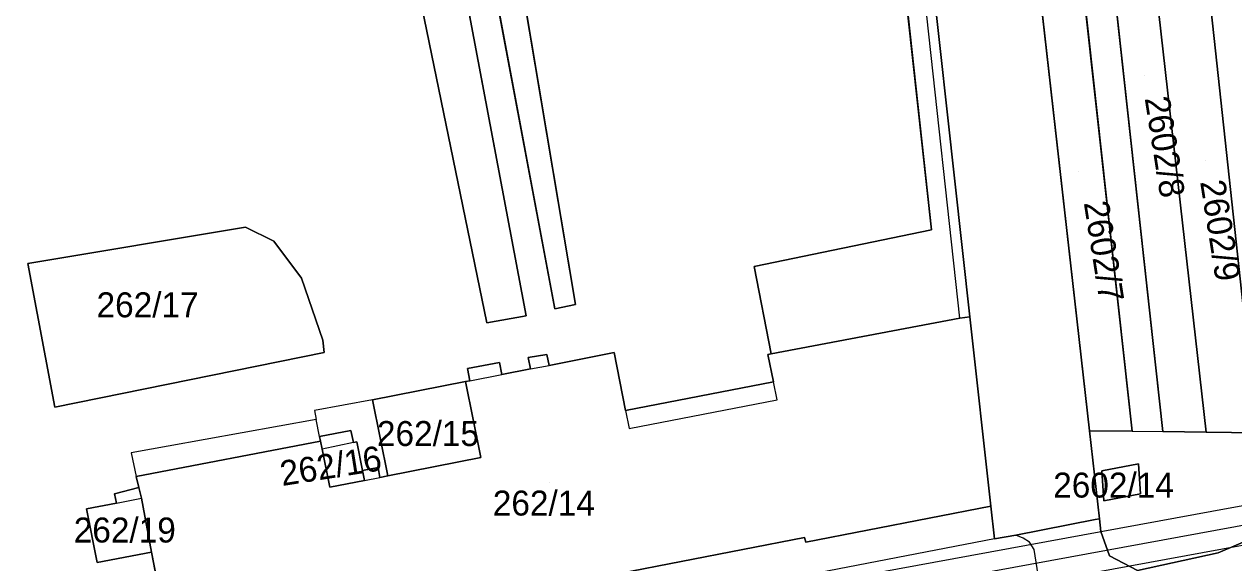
# Model space of a CAD drawing. Extents: x -263423 to -261326, y -1240067 to -1237864.
# Drawn here: x -263340.5 to -263243.6, y -1239342.6 to -1239299.5 of the extents above; entities that cross this region are included whole.
import ezdxf

# ---------------------------------------------------------------- set-up
doc = ezdxf.new("R2010")
doc.units = 0
for name, color, linetype in [('body_kn', 7, 'Continuous'), ('kladpar_druhypozemkov', 7, 'Continuous'), ('kladpar_hranice', 7, 'Continuous'), ('kladpar_parcelnecisla', 7, 'Continuous'), ('kladpar_plochy', 7, 'Continuous'), ('linie', 7, 'Continuous'), ('tarchy_linie', 7, 'Continuous'), ('zappar_hrandruhpozemk', 7, 'Continuous')]:
    doc.layers.add(name, color=color, linetype=linetype)

msp = doc.modelspace()

# ---------------------------------------------------------------- linework, layer by layer
at = {"layer": 'body_kn'}
for p, q in [((-263322.75, -1239315.73), (-263322.75, -1239315.73)), ((-263267.78, -1239315.94), (-263267.78, -1239315.94)), ((-263320.48, -1239316.83), (-263320.48, -1239316.83)), ((-263340.2, -1239318.63), (-263340.2, -1239318.63)), ((-263340.2, -1239318.63), (-263340.2, -1239318.63)), ((-263281.99, -1239318.86), (-263281.99, -1239318.86)), ((-263318.28, -1239319.81), (-263318.28, -1239319.81)), ((-263297.96, -1239322.25), (-263297.96, -1239322.25)), ((-263296.33, -1239321.92), (-263296.33, -1239321.92)), ((-263303.42, -1239323.37), (-263303.42, -1239323.37)), ((-263300.28, -1239322.81), (-263300.28, -1239322.81)), ((-263300.28, -1239322.81), (-263300.28, -1239322.81)), ((-263265.51, -1239323.01), (-263265.51, -1239323.01)), ((-263265.51, -1239323.01), (-263265.51, -1239323.01)), ((-263264.71, -1239322.89), (-263264.71, -1239322.89)), ((-263316.57, -1239324.78), (-263316.57, -1239324.78)), ((-263316.46, -1239325.77), (-263316.46, -1239325.77)), ((-263302.41, -1239326.55), (-263302.41, -1239326.55)), ((-263300.1, -1239326.17), (-263300.1, -1239326.17)), ((-263298.61, -1239325.92), (-263298.61, -1239325.92)), ((-263293.21, -1239325.77), (-263293.21, -1239325.77)), ((-263280.9, -1239325.92), (-263280.9, -1239325.92)), ((-263280.65, -1239325.87), (-263280.65, -1239325.87)), ((-263304.97, -1239327.05), (-263304.97, -1239327.05)), ((-263302.22, -1239327.53), (-263302.22, -1239327.53)), ((-263299.93, -1239327.08), (-263299.93, -1239327.08)), ((-263299.93, -1239327.08), (-263299.93, -1239327.08)), ((-263298.44, -1239326.79), (-263298.44, -1239326.79)), ((-263305.12, -1239328.09), (-263305.12, -1239328.09)), ((-263304.78, -1239328.03), (-263304.78, -1239328.03)), ((-263304.78, -1239328.03), (-263304.78, -1239328.03)), ((-263280.45, -1239328.1), (-263280.45, -1239328.1)), ((-263338.04, -1239330.14), (-263338.04, -1239330.14)), ((-263317.23, -1239330.4), (-263317.23, -1239330.4)), ((-263317.23, -1239330.4), (-263317.23, -1239330.4)), ((-263312.58, -1239329.55), (-263312.58, -1239329.55)), ((-263312.58, -1239329.55), (-263312.58, -1239329.55)), ((-263292.31, -1239330.41), (-263292.31, -1239330.41)), ((-263292.31, -1239330.41), (-263292.31, -1239330.41)), ((-263280.15, -1239329.55), (-263280.15, -1239329.55)), ((-263280.15, -1239329.55), (-263280.15, -1239329.55)), ((-263317.09, -1239331.13), (-263317.09, -1239331.13)), ((-263317.09, -1239331.13), (-263317.09, -1239331.13)), ((-263314.31, -1239332.01), (-263314.31, -1239332.01)), ((-263292.02, -1239331.86), (-263292.02, -1239331.86)), ((-263292.02, -1239331.86), (-263292.02, -1239331.86)), ((-263255.13, -1239332.03), (-263255.13, -1239332.03)), ((-263251.72, -1239332.06), (-263251.72, -1239332.06)), ((-263251.72, -1239332.06), (-263251.72, -1239332.06)), ((-263249.26, -1239332.09), (-263249.26, -1239332.09)), ((-263245.77, -1239332.15), (-263245.77, -1239332.15)), ((-263316.82, -1239332.5), (-263316.82, -1239332.5)), ((-263316.82, -1239332.5), (-263316.82, -1239332.5)), ((-263316.75, -1239332.86), (-263316.75, -1239332.86)), ((-263316.75, -1239332.86), (-263316.75, -1239332.86)), ((-263314.11, -1239332.97), (-263314.11, -1239332.97)), ((-263314.11, -1239332.97), (-263314.11, -1239332.97)), ((-263313.83, -1239332.91), (-263313.83, -1239332.91)), ((-263331.93, -1239333.8), (-263331.93, -1239333.8)), ((-263331.93, -1239333.8), (-263331.93, -1239333.8)), ((-263316.62, -1239333.49), (-263316.62, -1239333.49)), ((-263303.89, -1239334.18), (-263303.89, -1239334.18)), ((-263313.38, -1239335.22), (-263313.38, -1239335.22)), ((-263312.14, -1239334.98), (-263312.14, -1239334.98)), ((-263254.14, -1239335.23), (-263254.14, -1239335.23)), ((-263254.14, -1239335.23), (-263254.14, -1239335.23)), ((-263251.2, -1239334.68), (-263251.2, -1239334.68)), ((-263331.53, -1239335.68), (-263331.53, -1239335.68)), ((-263313.22, -1239336), (-263313.22, -1239336)), ((-263313.22, -1239336), (-263313.22, -1239336)), ((-263311.99, -1239335.76), (-263311.99, -1239335.76)), ((-263311.35, -1239335.63), (-263311.35, -1239335.63)), ((-263311.35, -1239335.63), (-263311.35, -1239335.63)), ((-263333.26, -1239337.07), (-263333.26, -1239337.07)), ((-263331.3, -1239336.58), (-263331.3, -1239336.58)), ((-263316, -1239336.54), (-263316, -1239336.54)), ((-263251.03, -1239337.08), (-263251.03, -1239337.08)), ((-263333.11, -1239337.82), (-263333.11, -1239337.82)), ((-263333.11, -1239337.82), (-263333.11, -1239337.82)), ((-263331.09, -1239337.42), (-263331.09, -1239337.42)), ((-263331.09, -1239337.42), (-263331.09, -1239337.42)), ((-263263.04, -1239338.07), (-263263.04, -1239338.07)), ((-263253.97, -1239337.63), (-263253.97, -1239337.63)), ((-263243.72, -1239338.18), (-263243.72, -1239338.18)), ((-263335.5, -1239338.29), (-263335.5, -1239338.29)), ((-263254.67, -1239339.14), (-263254.67, -1239339.14)), ((-263254.67, -1239339.14), (-263254.67, -1239339.14)), ((-263254.34, -1239339.08), (-263254.34, -1239339.08)), ((-263254.23, -1239340.09), (-263254.23, -1239340.09)), ((-263277.97, -1239340.58), (-263277.97, -1239340.58)), ((-263277.85, -1239340.95), (-263277.85, -1239340.95)), ((-263262.75, -1239340.68), (-263262.75, -1239340.68)), ((-263262.75, -1239340.68), (-263262.75, -1239340.68)), ((-263261.02, -1239340.38), (-263261.02, -1239340.38)), ((-263260.45, -1239340.64), (-263260.45, -1239340.64)), ((-263259.94, -1239340.96), (-263259.94, -1239340.96)), ((-263330.29, -1239341.75), (-263330.29, -1239341.75)), ((-263259.57, -1239341.53), (-263259.57, -1239341.53)), ((-263253.53, -1239342.05), (-263253.53, -1239342.05)), ((-263244.83, -1239341.82), (-263244.83, -1239341.82)), ((-263334.65, -1239342.57), (-263334.65, -1239342.57))]:
    msp.add_line(p, q, dxfattribs=at)
at = {"layer": 'kladpar_druhypozemkov'}
for p, q in [((-263250.71, -1239303.58), (-263250.71, -1239303.58)), ((-263245.82, -1239310.4), (-263245.82, -1239310.4)), ((-263256.04, -1239311.29), (-263256.04, -1239311.29)), ((-263329.96, -1239320.82), (-263329.96, -1239320.82)), ((-263307.62, -1239331.44), (-263307.62, -1239331.44)), ((-263314.67, -1239334.11), (-263314.67, -1239334.11)), ((-263298.44, -1239336.19), (-263298.44, -1239336.19)), ((-263252.48, -1239335.84), (-263252.48, -1239335.84)), ((-263332.65, -1239339.19), (-263332.65, -1239339.19))]:
    msp.add_line(p, q, dxfattribs=at)
at = {"layer": 'kladpar_hranice'}
for points in [[(-263254.67, -1239339.14), (-263261.02, -1239340.38), (-263262.75, -1239340.68), (-263263.04, -1239338.07), (-263264.71, -1239322.89), (-263268.9, -1239284.96), (-263273.11, -1239246.76), (-263274.93, -1239230.45), (-263274.97, -1239230.07), (-263276.29, -1239218.08), (-263279.7, -1239187.24), (-263281.03, -1239175.14), (-263282.73, -1239159.77), (-263283.91, -1239149.05), (-263286.63, -1239124.36), (-263290.39, -1239090.28)], [(-263228.94, -1239359.01), (-263232.6, -1239324.94), (-263236.39, -1239289.06), (-263237.7, -1239277.07), (-263241.63, -1239244.14), (-263243.01, -1239243.11), (-263245.1, -1239242.75), (-263246.01, -1239242.84), (-263251.52, -1239243.4), (-263255.64, -1239243.86), (-263258.95, -1239244.24), (-263261.36, -1239244.51), (-263263.54, -1239244.9), (-263264.39, -1239245.64), (-263264.94, -1239247.51), (-263262.98, -1239262.22), (-263262.49, -1239266.88), (-263255.13, -1239332.03), (-263254.34, -1239339.08), (-263254.67, -1239339.14)], [(-263244.09, -1239277.88), (-263247.38, -1239247.93), (-263247.85, -1239246.23), (-263249.91, -1239245.35), (-263251.31, -1239245.48), (-263251.52, -1239243.4), (-263246.01, -1239242.84), (-263242.19, -1239277.63), (-263237.7, -1239277.07), (-263236.39, -1239289.06), (-263240.85, -1239289.58), (-263236.07, -1239332.28), (-263234.28, -1239332.3), (-263236.08, -1239335.51), (-263237.48, -1239337.31), (-263240.67, -1239340.05), (-263244.83, -1239341.82), (-263251.27, -1239343.22), (-263253.53, -1239342.05), (-263254.23, -1239340.09), (-263254.34, -1239339.08), (-263255.13, -1239332.03)], [(-263255.13, -1239332.03), (-263251.72, -1239332.06), (-263258.71, -1239268.54), (-263262.49, -1239266.88), (-263262.98, -1239262.22), (-263259.18, -1239263.91), (-263261.36, -1239244.51)], [(-263261.36, -1239244.51), (-263258.95, -1239244.24), (-263256.64, -1239265.03), (-263253.21, -1239266.52), (-263248.84, -1239268.41), (-263246.58, -1239269.39), (-263248.21, -1239273.13), (-263252.68, -1239271.18), (-263256.12, -1239269.67), (-263249.26, -1239332.09), (-263245.77, -1239332.15), (-263241.72, -1239332.2), (-263238.03, -1239332.26), (-263242.78, -1239289.8), (-263246.26, -1239290.22), (-263247.62, -1239278.34), (-263244.09, -1239277.88)], [(-263262.49, -1239266.88), (-263258.71, -1239268.54), (-263251.72, -1239332.06), (-263255.13, -1239332.03), (-263262.49, -1239266.88)], [(-263307.79, -1239270), (-263297.96, -1239322.25), (-263296.33, -1239321.92), (-263301.05, -1239293.74)], [(-263301.05, -1239293.74), (-263296.33, -1239321.92), (-263297.96, -1239322.25), (-263307.79, -1239270)], [(-263256.12, -1239269.67), (-263252.68, -1239271.18), (-263245.77, -1239332.15), (-263249.26, -1239332.09), (-263256.12, -1239269.67)], [(-263252.68, -1239271.18), (-263248.21, -1239273.13), (-263247.62, -1239278.34), (-263246.26, -1239290.22), (-263241.72, -1239332.2), (-263245.77, -1239332.15), (-263252.68, -1239271.18)], [(-263303.42, -1239323.37), (-263300.28, -1239322.81), (-263309.63, -1239273.2), (-263313.62, -1239273.77), (-263303.42, -1239323.37)], [(-263300.28, -1239322.81), (-263303.42, -1239323.37), (-263313.62, -1239273.77), (-263309.63, -1239273.2), (-263300.28, -1239322.81)], [(-263268.9, -1239284.96), (-263264.71, -1239322.89), (-263265.51, -1239323.01), (-263280.65, -1239325.87), (-263281.99, -1239318.86), (-263267.78, -1239315.94), (-263270.77, -1239288.79)], [(-263270.77, -1239288.79), (-263267.78, -1239315.94), (-263281.99, -1239318.86), (-263280.65, -1239325.87), (-263280.9, -1239325.92), (-263280.45, -1239328.1), (-263292.31, -1239330.41), (-263293.21, -1239325.77), (-263298.44, -1239326.79), (-263298.61, -1239325.92), (-263300.1, -1239326.17), (-263299.93, -1239327.08), (-263302.22, -1239327.53), (-263302.41, -1239326.55), (-263304.97, -1239327.05), (-263304.78, -1239328.03), (-263305.12, -1239328.09), (-263312.58, -1239329.55), (-263311.35, -1239335.63), (-263311.99, -1239335.76), (-263312.14, -1239334.98), (-263313.38, -1239335.22), (-263313.83, -1239332.91), (-263314.11, -1239332.97), (-263314.31, -1239332.01), (-263316.82, -1239332.5), (-263316.75, -1239332.86), (-263331.53, -1239335.68), (-263331.3, -1239336.58), (-263333.26, -1239337.07), (-263333.11, -1239337.82), (-263335.5, -1239338.29), (-263334.65, -1239342.57), (-263330.29, -1239341.75), (-263328.77, -1239349.65)], [(-263246.26, -1239290.22), (-263242.78, -1239289.8), (-263238.03, -1239332.26), (-263241.72, -1239332.2), (-263246.26, -1239290.22)], [(-263322.75, -1239315.73), (-263340.2, -1239318.63), (-263338.04, -1239330.14), (-263316.46, -1239325.77), (-263316.57, -1239324.78), (-263318.28, -1239319.81), (-263320.48, -1239316.83), (-263322.75, -1239315.73)], [(-263340.2, -1239318.63), (-263322.75, -1239315.73), (-263320.48, -1239316.83), (-263318.28, -1239319.81), (-263316.57, -1239324.78), (-263316.46, -1239325.77), (-263338.04, -1239330.14), (-263340.2, -1239318.63)], [(-263328.77, -1239349.65), (-263330.29, -1239341.75), (-263331.09, -1239337.42), (-263331.3, -1239336.58), (-263331.53, -1239335.68), (-263316.75, -1239332.86), (-263316.62, -1239333.49), (-263316, -1239336.54), (-263313.22, -1239336), (-263313.38, -1239335.22), (-263312.14, -1239334.98), (-263311.99, -1239335.76), (-263311.35, -1239335.63), (-263303.89, -1239334.18), (-263305.12, -1239328.09), (-263304.78, -1239328.03), (-263304.97, -1239327.05), (-263302.41, -1239326.55), (-263302.22, -1239327.53), (-263299.93, -1239327.08), (-263300.1, -1239326.17), (-263298.61, -1239325.92), (-263298.44, -1239326.79), (-263293.21, -1239325.77), (-263292.31, -1239330.41), (-263280.45, -1239328.1), (-263280.9, -1239325.92), (-263280.65, -1239325.87), (-263265.51, -1239323.01), (-263264.71, -1239322.89), (-263263.04, -1239338.07), (-263277.85, -1239340.95), (-263277.97, -1239340.58), (-263292.78, -1239343.45)], [(-263292.78, -1239343.45), (-263277.97, -1239340.58), (-263277.85, -1239340.95), (-263263.04, -1239338.07), (-263262.75, -1239340.68), (-263261.02, -1239340.38), (-263254.67, -1239339.14), (-263254.34, -1239339.08), (-263254.23, -1239340.09), (-263253.53, -1239342.05), (-263251.27, -1239343.22), (-263244.83, -1239341.82), (-263240.67, -1239340.05), (-263237.48, -1239337.31), (-263236.08, -1239335.51), (-263234.28, -1239332.3), (-263233.24, -1239329.66), (-263232.6, -1239324.94), (-263228.94, -1239359.01)], [(-263311.35, -1239335.63), (-263312.58, -1239329.55), (-263305.12, -1239328.09), (-263303.89, -1239334.18), (-263311.35, -1239335.63)], [(-263316.75, -1239332.86), (-263316.82, -1239332.5), (-263314.31, -1239332.01), (-263314.11, -1239332.97), (-263313.83, -1239332.91), (-263313.38, -1239335.22), (-263313.22, -1239336), (-263316, -1239336.54), (-263316.62, -1239333.49), (-263316.75, -1239332.86)], [(-263254.14, -1239335.23), (-263251.2, -1239334.68), (-263251.03, -1239337.08), (-263253.97, -1239337.63), (-263254.14, -1239335.23)], [(-263254.14, -1239335.23), (-263253.97, -1239337.63), (-263251.03, -1239337.08), (-263251.2, -1239334.68), (-263254.14, -1239335.23)], [(-263331.09, -1239337.42), (-263330.29, -1239341.75), (-263334.65, -1239342.57), (-263335.5, -1239338.29), (-263333.11, -1239337.82), (-263333.26, -1239337.07), (-263331.3, -1239336.58), (-263331.09, -1239337.42)]]:
    msp.add_lwpolyline(points, dxfattribs=at)
at = {"layer": 'kladpar_plochy'}
for p, q in [((-263262.49, -1239266.88), (-263255.13, -1239332.03)), ((-263251.72, -1239332.06), (-263258.71, -1239268.54)), ((-263307.79, -1239270), (-263297.96, -1239322.25)), ((-263256.12, -1239269.67), (-263249.26, -1239332.09)), ((-263300.28, -1239322.81), (-263309.63, -1239273.2)), ((-263313.62, -1239273.77), (-263303.42, -1239323.37)), ((-263264.71, -1239322.89), (-263268.9, -1239284.96)), ((-263270.77, -1239288.79), (-263267.78, -1239315.94)), ((-263296.33, -1239321.92), (-263301.05, -1239293.74)), ((-263322.75, -1239315.73), (-263340.2, -1239318.63)), ((-263320.48, -1239316.83), (-263322.75, -1239315.73)), ((-263267.78, -1239315.94), (-263281.99, -1239318.86)), ((-263318.28, -1239319.81), (-263320.48, -1239316.83)), ((-263340.2, -1239318.63), (-263338.04, -1239330.14)), ((-263281.99, -1239318.86), (-263280.65, -1239325.87)), ((-263316.57, -1239324.78), (-263318.28, -1239319.81)), ((-263297.96, -1239322.25), (-263296.33, -1239321.92)), ((-263303.42, -1239323.37), (-263300.28, -1239322.81)), ((-263263.04, -1239338.07), (-263264.71, -1239322.89)), ((-263316.46, -1239325.77), (-263316.57, -1239324.78)), ((-263338.04, -1239330.14), (-263316.46, -1239325.77)), ((-263302.41, -1239326.55), (-263304.97, -1239327.05)), ((-263302.22, -1239327.53), (-263302.41, -1239326.55)), ((-263298.61, -1239325.92), (-263300.1, -1239326.17)), ((-263300.1, -1239326.17), (-263299.93, -1239327.08)), ((-263298.44, -1239326.79), (-263298.61, -1239325.92)), ((-263293.21, -1239325.77), (-263298.44, -1239326.79)), ((-263292.31, -1239330.41), (-263293.21, -1239325.77)), ((-263280.65, -1239325.87), (-263280.9, -1239325.92)), ((-263280.9, -1239325.92), (-263280.45, -1239328.1)), ((-263304.97, -1239327.05), (-263304.78, -1239328.03)), ((-263299.93, -1239327.08), (-263302.22, -1239327.53)), ((-263305.12, -1239328.09), (-263312.58, -1239329.55)), ((-263304.78, -1239328.03), (-263305.12, -1239328.09)), ((-263280.45, -1239328.1), (-263292.31, -1239330.41)), ((-263312.58, -1239329.55), (-263311.35, -1239335.63)), ((-263314.31, -1239332.01), (-263316.82, -1239332.5)), ((-263314.11, -1239332.97), (-263314.31, -1239332.01)), ((-263254.34, -1239339.08), (-263255.13, -1239332.03)), ((-263255.13, -1239332.03), (-263251.72, -1239332.06)), ((-263255.13, -1239332.03), (-263254.34, -1239339.08)), ((-263249.26, -1239332.09), (-263245.77, -1239332.15)), ((-263245.77, -1239332.15), (-263241.72, -1239332.2)), ((-263316.75, -1239332.86), (-263331.53, -1239335.68)), ((-263316.82, -1239332.5), (-263316.75, -1239332.86)), ((-263313.83, -1239332.91), (-263314.11, -1239332.97)), ((-263313.38, -1239335.22), (-263313.83, -1239332.91)), ((-263312.14, -1239334.98), (-263313.38, -1239335.22)), ((-263311.99, -1239335.76), (-263312.14, -1239334.98)), ((-263251.2, -1239334.68), (-263254.14, -1239335.23)), ((-263254.14, -1239335.23), (-263253.97, -1239337.63)), ((-263251.03, -1239337.08), (-263251.2, -1239334.68)), ((-263331.53, -1239335.68), (-263331.3, -1239336.58)), ((-263311.35, -1239335.63), (-263311.99, -1239335.76)), ((-263331.3, -1239336.58), (-263333.26, -1239337.07)), ((-263333.26, -1239337.07), (-263333.11, -1239337.82)), ((-263253.97, -1239337.63), (-263251.03, -1239337.08)), ((-263333.11, -1239337.82), (-263335.5, -1239338.29)), ((-263262.75, -1239340.68), (-263263.04, -1239338.07)), ((-263335.5, -1239338.29), (-263334.65, -1239342.57)), ((-263254.67, -1239339.14), (-263261.02, -1239340.38)), ((-263254.34, -1239339.08), (-263254.67, -1239339.14)), ((-263254.23, -1239340.09), (-263254.34, -1239339.08)), ((-263253.53, -1239342.05), (-263254.23, -1239340.09)), ((-263240.67, -1239340.05), (-263244.83, -1239341.82)), ((-263261.02, -1239340.38), (-263262.75, -1239340.68)), ((-263334.65, -1239342.57), (-263330.29, -1239341.75)), ((-263330.29, -1239341.75), (-263328.77, -1239349.65)), ((-263251.27, -1239343.22), (-263253.53, -1239342.05)), ((-263244.83, -1239341.82), (-263251.27, -1239343.22))]:
    msp.add_line(p, q, dxfattribs=at)
for points in [[(-263262.49, -1239266.88), (-263258.71, -1239268.54), (-263251.72, -1239332.06), (-263255.13, -1239332.03)], [(-263256.12, -1239269.67), (-263252.68, -1239271.18), (-263245.77, -1239332.15), (-263249.26, -1239332.09)], [(-263252.68, -1239271.18), (-263248.21, -1239273.13), (-263247.62, -1239278.34), (-263246.26, -1239290.22), (-263241.72, -1239332.2), (-263245.77, -1239332.15)], [(-263300.28, -1239322.81), (-263303.42, -1239323.37), (-263313.62, -1239273.77), (-263309.63, -1239273.2)], [(-263246.26, -1239290.22), (-263242.78, -1239289.8), (-263238.03, -1239332.26), (-263241.72, -1239332.2)], [(-263340.2, -1239318.63), (-263322.75, -1239315.73), (-263320.48, -1239316.83), (-263318.28, -1239319.81), (-263316.57, -1239324.78), (-263316.46, -1239325.77), (-263338.04, -1239330.14)], [(-263311.35, -1239335.63), (-263312.58, -1239329.55), (-263305.12, -1239328.09), (-263303.89, -1239334.18)], [(-263316.75, -1239332.86), (-263316.82, -1239332.5), (-263314.31, -1239332.01), (-263314.11, -1239332.97), (-263313.83, -1239332.91), (-263313.38, -1239335.22), (-263313.22, -1239336), (-263316, -1239336.54), (-263316.62, -1239333.49)], [(-263254.14, -1239335.23), (-263251.2, -1239334.68), (-263251.03, -1239337.08), (-263253.97, -1239337.63)], [(-263331.09, -1239337.42), (-263330.29, -1239341.75), (-263334.65, -1239342.57), (-263335.5, -1239338.29), (-263333.11, -1239337.82), (-263333.26, -1239337.07), (-263331.3, -1239336.58)]]:
    msp.add_lwpolyline(points, close=True, dxfattribs=at)
for points in [[(-263301.05, -1239293.74), (-263296.33, -1239321.92), (-263297.96, -1239322.25), (-263307.79, -1239270)], [(-263268.9, -1239284.96), (-263264.71, -1239322.89), (-263265.51, -1239323.01), (-263280.65, -1239325.87), (-263281.99, -1239318.86), (-263267.78, -1239315.94), (-263270.77, -1239288.79)], [(-263328.77, -1239349.65), (-263330.29, -1239341.75), (-263331.09, -1239337.42), (-263331.3, -1239336.58), (-263331.53, -1239335.68), (-263316.75, -1239332.86), (-263316.62, -1239333.49), (-263316, -1239336.54), (-263313.22, -1239336), (-263313.38, -1239335.22), (-263312.14, -1239334.98), (-263311.99, -1239335.76), (-263311.35, -1239335.63), (-263303.89, -1239334.18), (-263305.12, -1239328.09), (-263304.78, -1239328.03), (-263304.97, -1239327.05), (-263302.41, -1239326.55), (-263302.22, -1239327.53), (-263299.93, -1239327.08), (-263300.1, -1239326.17), (-263298.61, -1239325.92), (-263298.44, -1239326.79), (-263293.21, -1239325.77), (-263292.31, -1239330.41), (-263280.45, -1239328.1), (-263280.9, -1239325.92), (-263280.65, -1239325.87), (-263265.51, -1239323.01), (-263264.71, -1239322.89), (-263263.04, -1239338.07), (-263277.85, -1239340.95), (-263277.97, -1239340.58), (-263292.78, -1239343.45)], [(-263292.78, -1239343.45), (-263277.97, -1239340.58), (-263277.85, -1239340.95), (-263263.04, -1239338.07), (-263262.75, -1239340.68), (-263261.02, -1239340.38), (-263254.67, -1239339.14), (-263254.34, -1239339.08), (-263254.23, -1239340.09), (-263253.53, -1239342.05), (-263251.27, -1239343.22), (-263244.83, -1239341.82), (-263240.67, -1239340.05), (-263237.48, -1239337.31), (-263236.08, -1239335.51), (-263234.28, -1239332.3), (-263233.24, -1239329.66), (-263232.6, -1239324.94), (-263228.94, -1239359.01)]]:
    msp.add_lwpolyline(points, dxfattribs=at)
at = {"layer": 'linie'}
msp.add_lwpolyline([(-263422.67, -1239368.54), (-263341.02, -1239352.96), (-263336.01, -1239352.01), (-263334.98, -1239351.81), (-263328.56, -1239350.6), (-263292.96, -1239343.85), (-263292.78, -1239343.45), (-263277.97, -1239340.58), (-263277.85, -1239340.95), (-263263.04, -1239338.07), (-263264.71, -1239322.89), (-263268.9, -1239284.96), (-263273.11, -1239246.76), (-263274.93, -1239230.45), (-263274.97, -1239230.07), (-263276.29, -1239218.08), (-263279.7, -1239187.24), (-263281.03, -1239175.14), (-263282.73, -1239159.77), (-263283.91, -1239149.05), (-263286.63, -1239124.36), (-263290.39, -1239090.28)], dxfattribs=at)
at = {"layer": 'tarchy_linie'}
for points in [[(-263422.26, -1239370.92), (-263243.72, -1239338.18), (-263226.18, -1239334.99), (-263231.3, -1239288.44), (-263237.71, -1239236.19), (-263273.32, -1239240.37), (-263273.7, -1239237.1), (-263238.07, -1239232.9), (-263238.15, -1239232.1), (-263270.3, -1239235.29), (-263274.32, -1239235.95), (-263274.49, -1239234.41), (-263274.66, -1239232.88), (-263270.86, -1239232.25), (-263238.49, -1239229.03), (-263244.99, -1239168.98), (-263252.22, -1239103.44), (-263258.57, -1239048)], [(-263220.98, -1239335.65), (-263243.44, -1239339.73), (-263421.96, -1239372.47)], [(-263277.3, -1239350.37), (-263225.48, -1239341.29), (-263225.82, -1239338.13), (-263243.16, -1239341.28), (-263421.65, -1239374.01)]]:
    msp.add_lwpolyline(points, dxfattribs=at)
at = {"layer": 'zappar_hrandruhpozemk'}
for p, q in [((-263265.51, -1239323.01), (-263269.66, -1239285.04)), ((-263304.78, -1239328.03), (-263302.22, -1239327.53)), ((-263299.93, -1239327.08), (-263298.44, -1239326.79)), ((-263280.15, -1239329.55), (-263280.45, -1239328.1)), ((-263312.58, -1239329.55), (-263317.23, -1239330.4)), ((-263317.23, -1239330.4), (-263317.09, -1239331.13)), ((-263292.31, -1239330.41), (-263292.02, -1239331.86)), ((-263292.02, -1239331.86), (-263280.15, -1239329.55)), ((-263317.09, -1239331.13), (-263331.93, -1239333.8)), ((-263316.82, -1239332.5), (-263317.09, -1239331.13)), ((-263251.72, -1239332.06), (-263249.26, -1239332.09)), ((-263314.11, -1239332.97), (-263316.62, -1239333.49)), ((-263331.93, -1239333.8), (-263331.53, -1239335.68)), ((-263313.22, -1239336), (-263311.99, -1239335.76)), ((-263333.11, -1239337.82), (-263331.09, -1239337.42)), ((-263262.75, -1239340.68), (-263324.29, -1239352.54))]:
    msp.add_line(p, q, dxfattribs=at)
msp.add_lwpolyline([(-263259.08, -1239344.59), (-263259.57, -1239341.53), (-263259.94, -1239340.96), (-263260.45, -1239340.64), (-263261.02, -1239340.38)], dxfattribs=at)

# ---------------------------------------------------------------- texts
at = {"layer": 'kladpar_parcelnecisla'}
for s, rotation, p in [('2602/8', 279, (-263250.712, -1239305.391)), ('2602/9', 279, (-263246.268, -1239312.084)), ('2602/7', 279, (-263255.591, -1239313.761)), ('262/16', 9, (-263319.821, -1239336.459))]:
    msp.add_text(s, height=2, rotation=rotation, dxfattribs=at).set_placement(p)
for s, p in [('262/17', (-263334.697, -1239322.94)), ('262/15', (-263312.229, -1239333.25)), ('2602/14', (-263258.036, -1239337.38)), ('262/14', (-263302.944, -1239338.82)), ('262/19', (-263336.524, -1239340.98))]:
    msp.add_text(s, height=2, dxfattribs=at).set_placement(p)

doc.saveas('drawing.dxf')
